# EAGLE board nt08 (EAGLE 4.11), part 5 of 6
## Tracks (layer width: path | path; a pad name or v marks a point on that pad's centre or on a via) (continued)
SH_DTB  (via drill 0.61) (continued)
  Top 0.254: IC100.3 438.15,454.66 436.88,455.93 v436.88,458.47 436.88,488.95 438.15,490.22 IC101.3 438.15,492.76 436.88,494.03 436.88,527.05 438.15,528.32 IC102.3 438.15,530.86 440.06,532.76 | 440.06,532.76 440.69,533.4 440.69,535.94 IC102.11 | 440.06,532.76 441.96,530.86 441.96,528.32 441.32,527.68 441.32,501.01 440.69,500.38 IC101.11 | v278.13,247.01 278.13,245.11 IC62.3 | v280.67,247.65 280.67,250.19 IC62.11 280.67,252.73 281.94,254 281.94,287.02 280.67,288.29 IC63.11 280.67,290.83 281.94,292.1 281.94,321.31 278.76,324.49 | v278.13,287.02 278.13,283.21 IC63.3 | v34.29,323.85 34.29,264.16 35.56,262.89 IC13.2 | 278.76,324.49 278.13,323.85 278.13,321.31 IC64.3 | 278.76,324.49 280.67,326.39 IC64.11 | v283.85,332.11 283.85,354.96 285.75,356.87 IC65.6 | v351.79,451.49 351.15,450.85 v351.15,362.58
  Bottom 0.254: v436.88,458.47 438.15,458.47 440.06,460.38 IC100.11 | v278.13,247.01 278.76,247.65 v280.67,247.65 | v278.13,287.02 280.04,288.93 IC63.11 | v34.29,323.85 34.92,323.21 182.25,323.21 184.15,321.31 271.78,321.31 272.42,321.94 276.23,321.94 277.5,320.68 IC64.3 | v283.85,332.11 280.67,328.93 IC64.11 | v351.79,451.49 436.25,451.49 437.51,452.75 IC100.3 | v351.15,362.58 288.93,362.58 285.75,359.41 IC65.6
SH_EN  (via drill 0.61)
  Top 0.254: v194.94,27.3 194.94,11.43 78.74,11.43 75.56,14.61 IC16.2 | IC105.1 472.44,43.18 472.44,38.1 v461.01,26.67 461.01,4.45 473.07,4.45 474.35,5.71 IC104.2 | v177.8,483.87 184.15,490.22 184.15,549.91 212.72,578.49 350.52,578.49 | 350.52,578.49 v379.73,578.49 | v353.06,26.67 353.69,27.3 353.69,54.61 354.96,55.88 354.96,148.59 354.33,149.22 354.33,276.23 351.79,278.76 351.79,330.83 349.88,332.74 349.88,488.95 350.52,489.58 350.52,578.49
  Bottom 0.254: v194.94,27.3 195.58,26.67 285.12,26.67 285.75,26.04 353.06,26.04 | 353.06,26.04 460.38,26.04 v461.01,26.67 | v177.8,483.87 35.56,483.87 35.56,478.79 36.2,478.15 36.83,478.15 36.83,473.71 IC15.2 | v379.73,578.49 382.27,575.95 433.7,575.95 434.98,577.22 IC103.2 | v353.06,26.67 353.06,26.04
SH_EN\  (via drill 0.61)
  Top 0.254: IC104.4 480.69,5.71 481.96,4.45 483.87,4.45 483.87,49.53 485.14,50.8 IC105.9 | v80.01,273.05 80.01,260.35 78.74,259.08 78.74,242.57 79.38,241.94 79.38,100.97 80.01,100.33 IC17.11 | v36.83,282.57 36.83,443.87 34.29,446.4 34.29,471.17 IC15.1 | v36.2,546.74 31.75,542.29 v31.75,476.25 | v361.95,68.58 v366.39,64.14 | v147.32,73.66 128.27,92.71 v128.27,95.25
  Bottom 0.254: v80.01,273.05 70.48,282.57 v36.83,282.57 | v36.2,546.74 72.39,546.74 95.89,570.23 247.65,570.23 249.56,568.33 300.99,568.33 304.8,572.13 444.5,572.13 444.5,579.12 443.87,579.75 442.6,579.75 441.32,578.49 IC103.4 | v31.75,476.25 34.29,473.71 IC15.1 | v366.39,64.14 473.07,64.14 484.5,52.7 IC105.9 | v361.95,68.58 361.31,69.22 199.39,69.22 194.94,73.66 v147.32,73.66 | v128.27,95.25 122.56,100.97 81.92,100.97 80.64,99.69 IC17.11
SKP_RQ\  (via drill 0.61)
  Top 0.254: v92.71,191.13 92.71,100.33 85.09,92.71 IC17.6 | v184.78,193.68 186.06,194.94 186.06,312.42 186.69,313.06 v186.69,377.19 | v211.46,379.1 212.09,379.73 212.09,548 208.28,551.82 208.28,554.99 IC45.8
  Bottom 0.254: v92.71,191.13 95.25,193.68 v184.78,193.68 | v186.69,377.19 188.59,379.1 v211.46,379.1
SP_DY\  (via drill 0.61)
  Top 0.254: v515.62,146.05 515.62,121.92 518.16,119.38 IC114.12 | v-11.43,165.74 -19.05,173.35 -19.05,222.88 -26.04,229.87 -26.04,233.68 M916_20.F2
  Bottom 0.254: v515.62,146.05 514.99,146.69 412.12,146.69 406.4,152.4 374.65,152.4 370.2,156.84 267.97,156.84 259.08,165.74 v-11.43,165.74
ST_BLK_MK  (via drill 0.61)
  Top 0.254: v433.07,438.15 435.61,440.69 IC99.13 | v291.46,435.61 290.19,436.88 v290.19,445.77
  Bottom 0.254: v433.07,438.15 432.44,437.51 321.94,437.51 320.04,435.61 v291.46,435.61 | v290.19,445.77 288.93,447.04 252.73,447.04 252.09,446.4 67.31,446.4 64.77,443.87 64.77,440.69 M916_10.K1
ST_BLK_MK\  (via drill 0.61)
  Top 0.254: 45.09,18.41 45.72,19.05 45.72,21.59 IC9.9 | 45.09,18.41 v44.45,17.78 | v434.34,421 434.34,436.88 438.15,440.69 IC99.12 | v144.78,413.38 140.34,408.94 v140.34,406.4 | v61.59,398.78 61.59,252.73 60.33,251.46 v60.33,194.31 | v57.15,191.13 55.88,189.87 55.88,168.91 53.98,167 53.98,125.09 55.88,123.19 55.88,20.32 48.9,13.34 46.99,13.34 46.99,16.51 45.09,18.41
  Bottom 0.254: v44.45,17.78 35.56,17.78 33.66,15.88 IC9.1 | v434.34,421 433.7,420.37 379.1,420.37 372.11,413.38 v144.78,413.38 | v140.34,406.4 132.72,398.78 v61.59,398.78 | v60.33,194.31 v57.15,191.13
ST_CK  (via drill 0.61)
  Top 0.254: v38.1,254 38.1,195.58 IC12.12 | v-22.86,271.78 -22.23,272.42 -22.23,452.12 -11.43,462.92 -11.43,465.45 M916_23.M2 | v254.63,490.22 245.11,480.69 v245.11,453.39 | M916_10.P1 77.47,440.69 77.47,449.58 v80.64,452.75 80.64,453.39 v76.2,457.83
  Bottom 0.254: v38.1,254 37.47,254.63 -5.71,254.63 v-22.86,271.78 | M916_23.P2 -5.08,465.45 -7.62,462.92 M916_23.N2 -8.26,462.92 -10.79,465.45 M916_23.M2 -11.43,465.45 -12.7,464.19 -14.61,464.19 -15.24,463.55 -15.24,457.2 75.56,457.2 v76.2,457.83 | v254.63,490.22 278.76,514.35 363.22,514.35 368.3,509.27 471.17,509.27 471.81,509.9 IC111.1 | v245.11,453.39 244.47,452.75 v80.64,452.75
ST_CK\  (via drill 0.61)
  Top 0.254: v477.52,417.83 473.07,422.27 473.07,507.37 474.98,509.27 IC111.2
  Bottom 0.254: v477.52,417.83 489.58,417.83 490.22,418.46 512.45,418.46 514.99,415.93 IC120.2
ST_CK_0P  (via drill 0.61)
  Top 0.254: v446.4,46.99 447.04,47.62 447.04,125.73 449.58,128.27 v449.58,324.49 449.58,415.29 v450.21,415.93 | v445.77,420.37 445.77,427.99 440.69,433.07 IC99.4
  Bottom 0.254: v446.4,46.99 320.04,46.99 315.6,42.55 IC71.13 | v449.58,324.49 450.85,325.75 473.07,325.75 474.35,327.02 IC109.13 | v450.21,415.93 v445.77,420.37
ST_CK_0P\  (via drill 0.61)
  Top 0.254: v435.61,431.17 435.61,431.8 437.51,433.7 IC99.3 | v144.78,427.99 127,445.77 v127,463.55
  Bottom 0.254: v435.61,431.17 433.7,429.26 276.86,429.26 275.59,427.99 v144.78,427.99 | v127,463.55 126.36,464.19 -3.81,464.19 -6.99,461.01 -12.06,461.01 -13.34,462.28 M916_23.L2
ST_DATA  (via drill 0.61)
  Top 0.254: v409.57,-1.91 409.57,211.46 410.21,212.09 410.21,298.45 409.57,299.08 409.57,346.07 412.12,348.62 412.12,391.16 v415.93,394.97 | v523.24,403.23 525.78,405.76 525.78,414.02 IC120.6 | v472.44,403.23 472.44,508 473.71,509.27 473.71,512.45 475.62,512.45 476.88,511.18 IC111.3
  Bottom 0.254: v409.57,-1.91 314.32,-1.91 313.06,-3.17 IC70.1 | v415.93,394.97 424.18,403.23 v472.44,403.23 v523.24,403.23
ST_FINAL  (via drill 0.61)
  Top 0.254: v-40.01,80.01 -40.64,80.64 v-40.64,395.61 | v73.66,482.6 73.66,437.51 M916_10.N1
  Bottom 0.254: v-40.01,80.01 -22.86,62.87 41.27,62.87 42.55,61.59 IC10.10 | v-40.64,395.61 -6.99,429.26 50.8,429.26 53.98,432.44 66.67,432.44 71.12,436.88 73.03,436.88 M916_10.N1 | v73.66,482.6 213.36,482.6 214.63,481.33 283.21,481.33 284.48,482.6 394.97,482.6 396.88,480.69 IC90.12
ST_FINAL\  (via drill 0.61)
  Top 0.254: v468,189.87 466.09,191.77 v466.09,273.05 | v520.7,280.67 520.07,281.31 520.07,318.13 519.43,318.77 519.43,412.75 520.7,414.02 IC120.4
  Bottom 0.254: v468,189.87 471.81,189.87 474.35,187.32 IC107.2 | v466.09,273.05 473.71,280.67 v520.7,280.67
ST_IDLE  (via drill 0.61)
  Top 0.254: v482.6,449.58 482.6,509.27 IC111.5
  Bottom 0.254: v482.6,449.58 480.69,447.68 447.68,447.68 447.04,448.31 373.38,448.31 371.48,446.4 333.38,446.4 331.47,444.5 85.09,444.5 80.64,440.06 80.64,437.51 M916_10.R1
ST_IDLE\  (via drill 0.61)
  Top 0.254: v44.45,19.05 43.18,20.32 43.18,21.59 IC9.10 | v485.14,453.39 485.14,509.27 IC111.6 | v-33.66,426.08 -34.29,425.45 -34.29,37.47 -29.21,32.38 -29.21,19.68 -26.67,17.14 34.92,17.14 34.92,15.88 IC9.2
  Bottom 0.254: v44.45,19.05 45.72,19.05 45.72,17.78 44.45,16.51 43.81,17.14 37.47,17.14 36.2,15.88 IC9.2 | v485.14,453.39 481.96,450.21 307.34,450.21 302.89,454.66 53.34,454.66 51.44,452.75 -6.99,452.75 v-33.66,426.08
ST_REV_CK  (via drill 0.61)
  Top 0.254: IC140.5 602.62,528.96 601.35,528.96 IC140.4 600.71,528.32 593.09,520.7 v593.09,502.29 | v283.21,482.6 283.21,472.44 284.48,471.17 IC68.5 284.48,468.63 284.48,452.12 v278.13,445.77 | v405.13,447.04 405.13,469.9 406.4,471.17 406.4,473.71 405.13,474.98 405.13,478.79 IC90.9
  Bottom 0.254: v283.21,482.6 283.85,483.24 403.86,483.24 405.13,481.96 | 405.13,481.96 405.13,481.33 IC90.9 | v405.13,447.04 405.76,447.68 441.32,447.68 445.77,443.23 IC99.9 | v278.13,445.77 67.94,445.77 67.94,437.51 M916_10.L1 | v593.09,502.29 592.46,501.65 528.96,501.65 502.92,475.62 414.65,475.62 408.31,481.96 405.13,481.96
SWTM  (via drill 0.61)
  Top 0.254: v485.14,17.14 486.41,18.41 486.41,54.61 490.22,58.42 490.22,235.59 | 490.22,235.59 v489.58,236.22 | v490.86,370.84 490.22,370.2 490.22,235.59 | IC55.4 240.03,509.27 v240.03,430.53 240.03,405.13 IC54.11 240.03,402.59 241.3,401.32 241.3,381.63 v245.11,377.82 | v83.82,297.18 92.08,305.44 92.08,363.86 92.71,364.49 92.71,415.93 91.44,417.19 91.44,429.89 92.08,430.53 M916_10.V2
  Bottom 0.254: v485.14,17.14 484.5,17.14 482.6,15.24 IC104.10 | v489.58,236.22 495.3,241.94 518.79,241.94 520.07,243.21 IC117.4 | v490.86,370.84 481.33,370.84 475.62,376.56 IC110.2 474.35,376.56 468,370.2 333.38,370.2 325.75,377.82 v245.11,377.82 | v83.82,297.18 5.08,297.18 0.64,292.74 IC2.4 | v240.03,430.53 93.34,430.53 M916_10.V2
SWTM\  (via drill 0.61)
  Top 0.254: v490.86,387.99 492.12,386.71 492.12,328.93 490.86,327.66 490.86,112.39 493.39,109.86 493.39,5.71 491.49,3.81 478.79,3.81 478.79,11.43 477.52,12.7 IC104.12
  Bottom 0.254: v490.86,387.99 419.1,387.99 408.94,398.14 407.04,398.14 403.23,401.95 244.47,401.95 243.21,403.23 IC54.10
SYNC
  Top 0.254: IC66.10 283.85,403.23 285.12,403.23 IC66.9
SYNC-P\  (via drill 0.61)
  Top 0.254: IC73.1 312.42,113.03 314.96,115.57 314.96,118.11 IC73.13 314.96,120.65 312.42,123.19 312.42,166.37 IC74.1 312.42,168.91 314.96,171.45 314.96,173.99 IC74.13 314.96,176.53 312.42,179.07 312.42,186.69 IC75.1 312.42,189.23 314.96,191.77 314.96,194.31 IC75.13 | v289.56,361.31 289.56,367.03 288.93,367.67 288.93,393.7 289.56,394.33 289.56,401.32 288.29,402.59 IC66.8 | v309.25,358.77 310.51,357.5 v310.51,196.85
  Bottom 0.254: v289.56,361.31 292.1,358.77 v309.25,358.77 | v310.51,196.85 311.15,197.49 313.06,197.49 314.32,196.22 IC75.13
T3  (via drill 0.61)
  Top 0.254: v544.83,471.17 544.83,420.37 546.1,419.1 546.1,120.65 551.18,115.57 551.18,20.32 554.99,16.51 IC123.2
  Bottom 0.254: v544.83,471.17 570.87,497.2 596.26,497.2 | 596.26,497.2 597.53,498.48 IC139.12 | 596.26,497.2 601.35,497.2 602.62,498.48 IC139.10
T_00\  (via drill 0.61)
  Top 0.254: v313.69,287.02 v313.69,284.48 | M916_16.V2 372.75,208.91 373.38,209.55 373.38,283.85 372.75,284.48 M916_17.V2
  Bottom 0.254: v313.69,284.48 132.72,284.48 M916_8.V2 | v313.69,287.02 316.23,289.56 363.86,289.56 368.3,285.12 371.48,285.12 M916_17.V2
T_01\  (via drill 0.61)
  Top 0.254: v121.92,221.62 121.92,218.44 M916_7.S1 | v109.22,222.88 108.58,223.52 108.58,283.21 109.22,283.85 109.22,287.65 M916_8.M2 110.49,288.29 111.12,288.93 111.12,337.19 v114.94,341 | v347.35,337.82 347.35,296.55 347.98,295.91 347.98,289.56 349.25,288.29 M916_17.M2
  Bottom 0.254: v121.92,221.62 120.65,222.88 v109.22,222.88 | v347.35,337.82 341,344.17 187.96,344.17 186.06,342.26 116.2,342.26 v114.94,341
T_02\  (via drill 0.61)
  Top 0.254: v103.5,284.48 98.42,279.4 98.42,212.72 97.79,212.09 M916_7.H2
  Bottom 0.254: v103.5,284.48 105.41,286.38 111.12,286.38 | 111.12,286.38 112.39,285.12 M916_8.N2 | 111.12,286.38 132.72,286.38 133.99,285.12 313.06,285.12 314.32,286.38 351.15,286.38 352.43,285.12 M916_17.N2
T_03\  (via drill 0.61)
  Top 0.254: v106.68,279.4 107.31,278.76 107.31,276.23 104.78,273.69 104.78,208.91 100.97,208.91 M916_7.J2 | v116.2,279.4 116.2,287.65 M916_8.P2 | v356.87,259.08 356.87,287.65 M916_17.P2 | v290.19,249.56 v290.19,257.81 | v170.18,249.56 168.28,251.46 v168.28,273.05
  Bottom 0.254: v106.68,279.4 v116.2,279.4 121.92,273.69 167.64,273.69 v168.28,273.05 | v356.87,259.08 356.24,258.44 295.27,258.44 294.64,257.81 v290.19,257.81 | v290.19,249.56 173.35,249.56 172.72,250.19 170.81,250.19 v170.18,249.56
T_04\  (via drill 0.61)
  Top 0.254: v110.49,280.67 110.49,249.56 111.12,248.92 111.12,219.71 111.76,219.07 111.76,209.55 112.39,208.91 M916_7.N2 | v118.75,281.94 118.75,284.48 M916_8.R2 | v334.64,280.67 332.11,278.13 v332.11,276.86 | v243.21,276.86 245.11,274.95 v245.11,272.42
  Bottom 0.254: v118.75,281.94 111.76,281.94 v110.49,280.67 105.41,280.67 105.41,279.4 114.3,270.51 179.71,270.51 181.61,268.61 245.11,268.61 v245.11,272.42 | v334.64,280.67 354.96,280.67 358.77,284.48 M916_17.R2 | v332.11,276.86 331.47,277.5 243.84,277.5 v243.21,276.86
T_05\  (via drill 0.61)
  Top 0.254: v114.3,232.41 114.3,213.36 115.57,212.09 M916_7.P2 | v121.92,233.04 123.19,234.31 123.19,259.71 | 123.19,259.71 123.19,287.65 M916_8.S2 | v361.95,256.54 361.95,287.65 M916_17.S2 | v122.56,259.71 123.19,259.71
  Bottom 0.254: v114.3,232.41 114.94,233.04 v121.92,233.04 | v361.95,256.54 360.68,255.27 287.02,255.27 285.75,256.54 168.28,256.54 165.1,259.71 v122.56,259.71
T_06\  (via drill 0.61)
  Top 0.254: M916_8.T2 125.09,284.48 123.83,283.21 123.83,207.01 127.64,207.01 128.91,208.28 128.91,211.46 M916_7.U2 129.54,211.46 v132.08,211.46 | v362.58,220.34 362.58,229.87 366.39,233.68 366.39,284.48 M916_17.T2 | v147.32,217.17 146.69,216.53 v146.69,214
  Bottom 0.254: v362.58,220.34 361.95,219.71 291.46,219.71 289.56,217.81 276.86,217.81 275.59,216.53 147.96,216.53 v147.32,217.17 | v146.69,214 144.15,211.46 v132.08,211.46
T_07\  (via drill 0.61)
  Top 0.254: v127.64,208.28 127,208.91 127,217.81 124.46,220.34 124.46,260.99 | 124.46,260.99 124.46,281.31 128.27,285.12 128.27,287.65 M916_8.U2 | v368.3,261.62 368.3,287.65 M916_17.U2 | v125.09,260.99 124.46,260.99
  Bottom 0.254: v127.64,208.28 131.44,208.28 M916_7.V2 | v368.3,261.62 367.03,260.35 319.4,260.35 318.13,259.08 294.64,259.08 294,258.44 290.83,258.44 289.56,259.71 244.47,259.71 241.94,257.18 177.16,257.18 173.35,260.99 v125.09,260.99
T_FWD\  (via drill 0.61)
  Top 0.254: v90.81,219.71 89.53,220.98 89.53,244.47 90.81,245.75 90.81,265.43 | 90.81,265.43 90.81,287.65 M916_8.E2 | v336.55,271.14 336.55,287.65 M916_17.H2 | v91.44,265.43 90.81,265.43
  Bottom 0.254: v90.81,219.71 97.79,219.71 98.42,219.07 102.23,219.07 102.87,218.44 M916_7.K1 | v336.55,271.14 334.01,268.61 247.65,268.61 246.38,267.33 142.24,267.33 140.97,266.06 92.08,266.06 v91.44,265.43
T_GO\  (via drill 0.61)
  Top 0.254: v327.02,300.36 326.39,299.72 326.39,285.75 327.02,285.12 M916_17.D2 | v101.6,302.26 v97.16,297.81
  Bottom 0.254: v327.02,300.36 326.39,300.99 257.81,300.99 257.18,301.62 103.5,301.62 102.87,302.26 v101.6,302.26 | v97.16,297.81 87.63,288.29 85.09,288.29 M916_8.C2
T_PWR_CLR\  (via drill 0.61)
  Top 0.254: v115.57,290.83 114.94,290.19 114.94,279.4 117.47,276.86 v117.47,271.78 117.47,216.53 118.75,215.26 M916_7.R1 | v343.54,272.42 343.54,287.65 M916_17.K2
  Bottom 0.254: v115.57,290.83 113.67,292.74 104.14,292.74 99.69,288.29 97.79,288.29 M916_8.H2 | v343.54,272.42 327.02,272.42 326.39,273.05 326.39,276.23 284.48,276.23 281.94,273.69 170.18,273.69 168.28,271.78 v117.47,271.78
T_REV\  (via drill 0.61)
  Top 0.254: v107.95,283.85 107.95,215.9 107.31,215.26 M916_7.L1
  Bottom 0.254: 107.31,283.21 v107.95,283.85 | 107.31,283.21 95.89,283.21 94.61,284.48 M916_8.F2 | 107.31,283.21 132.72,283.21 133.35,283.85 288.93,283.85 289.56,283.21 338.45,283.21 339.73,284.48 M916_17.J2
T_SINGLE_UNIT\  (via drill 0.61)
  Top 0.254: v140.34,286.38 139.7,285.75 139.7,222.25 140.97,220.98 140.97,135.89 v140.34,135.25
  Bottom 0.254: v140.34,286.38 137.16,289.56 105.41,289.56 104.14,288.29 M916_8.K2 | v140.34,135.25 245.11,135.25 249.56,130.81 363.86,130.81 365.12,132.08 M916_15.T2
T_STOP\  (via drill 0.61)
  Top 0.254: M916_7.E1 90.17,218.44 88.9,219.71 88.9,245.11 90.17,246.38 90.17,282.57 88.27,284.48 M916_8.D2 | v330.83,271.14 330.83,287.65 M916_17.E2
  Bottom 0.254: v330.83,271.14 328.93,269.24 288.93,269.24 285.75,272.42 250.19,272.42 245.75,267.97 104.78,267.97 88.27,284.48 M916_8.D2
T_TRK  (via drill 0.61)
  Top 0.254: v265.43,194.31 v265.43,225.43 265.43,252.73 v267.33,254.63 | 12.7,257.81 7.62,252.73 7.62,243.84 M916_20.U1 | 12.7,257.81 v13.97,259.08 | v515.62,309.25 515.62,318.77 IC118.2 | v381.63,309.25 377.82,305.44 v377.82,226.06 | 12.7,257.81 12.7,302.89 14.61,304.8 14.61,473.07 11.43,473.07 10.16,474.35 10.16,476.88 8.89,478.15 M916_3.U2
  Bottom 0.254: v265.43,194.31 267.33,192.41 273.69,192.41 274.95,193.68 IC61.13 | v267.33,254.63 266.06,255.91 167.64,255.91 165.1,258.44 14.61,258.44 v13.97,259.08 | v381.63,309.25 v515.62,309.25 | v377.82,226.06 266.06,226.06 v265.43,225.43 | M916_20.S1 2.54,243.21 7.62,243.21 M916_20.U1
T_TRK\  (via drill 0.61)
  Top 0.254: v283.21,205.1 283.21,195.58 IC61.10 | v260.35,212.72 254.63,218.44 254.63,304.8 253.37,306.07 v253.37,374.01 | v15.88,387.35 15.24,387.99 15.24,473.71 13.97,474.98 12.06,474.98 M916_3.V2
  Bottom 0.254: v283.21,205.1 275.59,212.72 v260.35,212.72 | v253.37,374.01 251.46,375.92 118.11,375.92 106.68,387.35 v15.88,387.35
T_WRITE_OK\  (via drill 0.61)
  Top 0.254: 99.06,247.01 99.06,275.59 v103.5,280.04 | 99.06,247.01 99.06,212.09 98.42,211.46 98.42,136.53 97.79,135.89 M916_6.H2 | v106.05,281.94 106.05,284.48 M916_8.L2 | v347.35,256.54 347.35,284.48 M916_17.L2 | v269.24,257.81 264.16,252.73 v264.16,250.82 | v99.69,247.01 99.06,247.01
  Bottom 0.254: v103.5,280.04 105.41,281.94 v106.05,281.94 | v347.35,256.54 346.71,255.91 287.65,255.91 286.38,257.18 269.88,257.18 v269.24,257.81 | v264.16,250.82 263.52,250.19 173.99,250.19 173.35,250.82 168.28,250.82 165.1,247.65 100.33,247.65 v99.69,247.01
TIM  (via drill 0.61)
  Top 0.254: v48.26,460.38 48.26,496.57 44.45,500.38 IC6.5 | v125.73,459.11 125.09,458.47 125.09,374.01 128.27,370.84 M916_9.U1
  Bottom 0.254: v48.26,460.38 49.53,459.11 v125.73,459.11
TIM\  (via drill 0.61)
  Top 0.254: v38.1,131.44 38.1,120.65 36.83,119.38 36.83,116.84 34.29,114.3 34.29,55.88 35.56,54.61 IC10.2 | v121.92,147.32 122.56,147.96 v122.56,201.29 v122.56,207.65 | v60.33,488.31 60.33,440.06 62.87,437.51 62.87,266.7 62.23,266.06 62.23,201.93 v61.59,201.29
  Bottom 0.254: v38.1,131.44 53.98,147.32 v121.92,147.32 | v122.56,207.65 125.09,210.19 129.54,210.19 134.62,215.26 198.75,215.26 200.03,214 IC38.11 | v60.33,488.31 47.62,501.01 IC6.6 | v61.59,201.29 v122.56,201.29
TM_EN  (via drill 0.61)
  Top 0.254: IC117.11 520.7,252.73 523.24,255.27 523.24,317.5 524.51,318.77 524.51,382.27 525.78,383.54 IC119.9 | v514.35,388.62 514.35,450.85 513.08,452.12 IC121.1 | v488.95,464.19 488.95,520.07 487.05,520.07 485.77,518.79 IC111.9 485.14,519.43 485.14,526.41 v457.83,553.72 | v-1.27,544.83 -1.27,538.48 -2.54,537.21 -2.54,476.25 -1.91,475.62 M916_3.R2
  Bottom 0.254: v514.35,388.62 516.25,386.71 523.88,386.71 525.14,385.44 IC119.9 | v488.95,464.19 499.11,454.02 512.45,454.02 IC121.1 | v-1.27,544.83 -0.64,545.47 89.53,545.47 109.22,565.15 314.32,565.15 318.13,568.96 | 318.13,568.96 319.4,570.23 M916_13.R2 | v457.83,553.72 442.6,568.96 318.13,568.96
TM_EN\  (via drill 0.61)
  Top 0.254: v476.25,323.85 476.25,318.77 474.98,317.5 474.98,271.78 IC108.13 | IC111.8 487.68,516.89 483.87,513.08 483.87,330.2 482.6,328.93 IC109.10 | v128.91,314.96 134.62,309.25 v134.62,282.57 | v283.21,276.23 282.57,275.59 282.57,253.37 281.94,252.73 281.94,219.71 285.75,215.9 285.75,195.58 IC61.9
  Bottom 0.254: v476.25,323.85 478.79,326.39 478.79,329.56 480.69,329.56 481.96,328.3 IC109.10 | M916_21.J2 -19.68,310.51 -17.14,313.06 M916_21.K2 -16.51,313.69 -16.51,318.13 47.62,318.13 50.8,314.96 v128.91,314.96 | IC61.12 278.76,193.68 280.04,192.41 283.85,192.41 285.12,193.68 IC61.9 | v134.62,282.57 142.24,274.95 242.57,274.95 243.84,276.23 v283.21,276.23 283.85,276.86 327.66,276.86 330.2,274.32 349.88,274.32 350.52,274.95 434.34,274.95 437.51,271.78 466.09,271.78 466.73,272.42 473.07,272.42 474.35,271.14 IC108.13
TP00  (via drill 0.61)
  Top 0.254: IC73.3 317.5,113.03 320.04,115.57 320.04,118.11 IC73.11 319.4,120.02 319.4,164.47 317.5,166.37 IC74.3 317.5,168.91 v317.5,172.72 | v522.61,180.34 522.61,201.29 523.24,201.93 IC116.5 | v290.83,361.31 290.19,361.95 v290.19,393.7 | v275.59,393.06 275.59,394.97 IC66.2 275.59,397.51 275.59,402.59 IC66.13 275.59,405.13 v275.59,429.26 | v65.41,253.37 65.41,407.67 66.04,408.31 66.04,414.02 v64.77,415.29 | v-1.91,427.99 -1.91,440.06 -2.54,440.69 IC5.3 | M916_2.M2 71.12,421 73.03,419.1 73.03,418.46 M916_2.N2 | v308.61,173.35 307.34,174.62 307.34,196.22 308.61,197.49 308.61,356.87 307.98,357.5 v307.98,361.31
  Bottom 0.254: v522.61,180.34 427.99,180.34 426.08,182.25 344.17,182.25 334.64,172.72 v317.5,172.72 316.87,173.35 v308.61,173.35 | v290.83,361.31 v307.98,361.31 311.79,361.31 314.32,358.77 IC78.2 | v290.19,393.7 289.56,393.06 v275.59,393.06 | IC66.12 277.5,403.23 276.23,403.23 IC66.13 | v65.41,253.37 85.72,253.37 87,252.09 IC18.8 | M916_2.N2 73.03,417.83 71.75,416.56 66.04,416.56 v64.77,415.29 48.9,415.29 37.47,426.72 -0.64,426.72 v-1.91,427.99 | M916_2.M2 71.12,421 76.2,421 M916_2.P2 77.47,421.64 78.74,422.91 87,422.91 93.34,429.26 v275.59,429.26
TP00\  (via drill 0.61)
  Top 0.254: IC18.13 75.56,250.82 76.83,250.82 IC18.12 | IC18.10 83.19,250.82 84.45,250.82 IC18.9 85.09,250.19 85.09,245.11 IC18.6 | v318.77,201.93 318.77,194.31 318.13,193.68 318.13,189.87 317.5,189.23 IC75.3 | v182.88,206.38 v182.88,251.46
  Bottom 0.254: v318.77,201.93 318.13,201.29 276.86,201.29 276.23,200.66 188.59,200.66 v182.88,206.38 | v182.88,251.46 167.64,251.46 164.47,248.28 89.53,248.28 85.72,244.47 IC18.6 | IC18.12 78.11,250.82 79.38,249.56 80.64,249.56 81.92,250.82 IC18.10
TP00_A  (via drill 0.61)
  Top 0.254: v169.54,265.43 170.18,266.06 v170.18,372.75 | v280.67,373.38 283.21,370.84 283.21,367.03 IC65.10 | v478.79,357.5 478.79,322.58 480.06,321.31 IC109.4 | v331.47,370.84 v344.81,357.5
  Bottom 0.254: v169.54,265.43 93.98,265.43 92.71,264.16 88.9,264.16 87,262.25 IC19.6 | v170.18,372.75 262.25,372.75 262.89,373.38 v280.67,373.38 328.93,373.38 v331.47,370.84 | v344.81,357.5 v478.79,357.5
TP00_A\  (via drill 0.61)
  Top 0.254: IC19.1 74.3,260.99 75.56,260.99 IC19.2 | v63.5,266.06 63.5,417.83 66.67,417.83 M916_2.L2
  Bottom 0.254: IC19.5 83.19,260.99 81.92,260.99 IC19.4 80.64,262.25 79.38,263.52 78.11,263.52 76.83,262.25 IC19.2 | v63.5,266.06 67.31,262.25 73.03,262.25 IC19.1
TP0_XTLK_DY\  (via drill 0.61)
  Top 0.254: 65.41,421 64.77,421 M916_2.K2 | 65.41,421 66.67,421 68.58,419.1 68.58,321.31 77.47,312.42 77.47,308.61 76.83,307.98 76.83,272.42 78.74,270.51 IC19.12 | v61.59,465.45 65.41,461.64 65.41,421
  Bottom 0.254: v61.59,465.45 53.98,465.45 47.62,471.81 IC15.6 | M916_2.J2 60.33,418.46 59.69,419.1 57.78,419.1 56.52,420.37 56.52,422.91 62.23,422.91 63.5,421.64 M916_2.K2
TP01  (via drill 0.61)
  Top 0.254: v482.6,167 482.6,119.38 IC106.10 | v515.62,177.16 514.99,177.8 514.99,202.56 IC116.2 | M916_12.N2 313.06,494.67 311.15,496.57 311.15,497.2 M916_12.M2 | v54.61,23.5 49.53,28.57 49.53,73.03 | 49.53,73.03 49.53,74.93 48.9,75.56 48.9,108.58 49.53,109.22 v49.53,317.5 | v86.36,493.39 84.45,491.49 84.45,372.75 86.36,370.84 86.36,322.58 85.09,321.31 IC20.6 | v306.07,108.58 302.89,105.41 v302.89,76.2 | 49.53,73.03 v51.44,74.93
  Bottom 0.254: v482.6,167 492.76,177.16 v515.62,177.16 | M916_12.P2 316.23,497.2 313.69,494.67 M916_12.N2 313.06,494.03 307.98,488.95 203.84,488.95 199.39,493.39 v86.36,493.39 | v54.61,23.5 57.15,20.95 80.64,20.95 81.92,22.23 IC16.10 | v49.53,317.5 50.16,318.13 83.19,318.13 84.45,319.4 IC20.6 | v306.07,108.58 327.02,108.58 338.45,120.02 438.79,120.02 442.6,116.2 480.69,116.2 481.96,117.47 IC106.10 | v302.89,76.2 301.62,74.93 v51.44,74.93
TP01\  (via drill 0.61)
  Top 0.254: IC20.1 73.03,319.4 74.3,319.4 IC20.2 | 82.55,267.33 87,267.33 88.27,268.61 IC19.8 | 82.55,267.33 82.55,318.77 IC20.5 | v75.56,179.71 74.93,180.34 74.93,241.3 73.66,242.57 v73.66,246.38 | v80.01,247.65 81.28,248.92 81.28,259.08 82.55,260.35 82.55,267.33
  Bottom 0.254: IC20.5 81.92,319.4 80.64,319.4 IC20.4 79.38,320.68 78.11,321.94 76.83,321.94 75.56,320.68 IC20.2 | v75.56,179.71 136.53,179.71 137.79,178.44 178.44,178.44 181.61,175.26 304.17,175.26 306.07,177.16 318.13,177.16 319.4,175.9 IC74.11 | v73.66,246.38 74.93,247.65 v80.01,247.65
TP01_A  (via drill 0.61)
  Top 0.254: v361.95,81.92 370.2,90.17 370.2,143.51 364.49,149.22 v364.49,230.5 | v180.34,330.2 184.15,326.39 v184.15,322.58 | v371.48,323.85 370.84,323.21 370.84,231.14 v371.48,230.5
  Bottom 0.254: v361.95,81.92 349.25,81.92 345.44,78.11 319.4,78.11 318.13,79.38 IC72.12 | v364.49,230.5 v371.48,230.5 452.75,230.5 475.62,253.37 521.34,253.37 522.61,252.09 IC117.10 | v180.34,330.2 90.17,330.2 88.27,328.3 IC20.8 | v184.15,322.58 294.64,322.58 295.91,323.85 v371.48,323.85
TP01_A\  (via drill 0.61)
  Top 0.254: IC20.13 75.56,327.02 76.83,327.02 IC20.12 | IC20.10 83.19,327.02 84.45,327.02 IC20.9 | v300.99,341 300.99,488.31 306.7,494.03 M916_12.L2
  Bottom 0.254: v300.99,341 300.36,341.63 206.38,341.63 197.49,332.74 90.17,332.74 87,329.56 | 87,329.56 85.72,328.3 IC20.9 | 87,329.56 79.38,329.56 78.11,328.3 IC20.12
TP1_XTLK_DY\  (via drill 0.61)
  Top 0.254: M916_12.H2 298.45,497.2 300.36,495.3 300.36,494.67 M916_12.J2 300.36,494.03 297.18,490.86 v297.18,455.93 | v52.07,482.6 52.7,481.96 v52.7,455.3 52.7,419.74 51.44,418.46 v51.44,247.65
  Bottom 0.254: v52.07,482.6 41.91,482.6 40.01,480.69 IC15.12 | v51.44,247.65 53.34,245.75 73.03,245.75 74.3,244.47 IC18.2 | v297.18,455.93 296.55,455.3 v52.7,455.3
TS03\  (via drill 0.61)
  Top 0.254: v327.66,382.27 v327.66,451.49 | M916_23.H2 -22.86,465.45 -20.95,463.55 -20.95,462.92 M916_23.J2 -19.68,462.92 -19.68,463.55 -17.78,465.45 M916_23.K2
  Bottom 0.254: v327.66,382.27 392.43,382.27 396.88,377.82 IC88.3 | v327.66,451.49 321.94,457.2 76.83,457.2 76.2,456.56 -15.88,456.56 -19.68,460.38 -19.68,462.28 M916_23.J2
U+M_DY\  (via drill 0.61)
  Top 0.254: v-29.21,241.94 -29.21,237.49 M916_20.E2 | v468.63,377.19 v468.63,319.4 468.63,267.97 472.44,264.16 IC108.1 | v384.18,325.12 386.08,323.21 v386.08,320.04
  Bottom 0.254: M916_20.N1 -8.26,240.66 -9.53,241.94 v-29.21,241.94 -30.48,241.94 -43.81,255.27 -43.81,325.75 73.03,325.75 74.3,324.49 274.95,324.49 275.59,325.12 v384.18,325.12 | v468.63,377.19 474.98,383.54 IC110.13 | v386.08,320.04 386.71,319.4 v468.63,319.4
USR_00  (via drill 0.61)
  Top 0.254: v78.11,273.69 78.74,274.32 78.74,286.38 79.38,287.02 79.38,318.13 78.74,318.77 78.74,362.58 79.38,363.22 79.38,369.57 78.74,370.2 M916_9.A1 | v114.94,518.79 97.16,501.01 v97.16,386.08
  Bottom 0.254: v78.11,273.69 -0.64,273.69 -8.26,266.06 IC1.22 | v114.94,518.79 135.25,539.12 235.59,539.12 236.85,537.85 IC56.12 | v97.16,386.08 81.92,370.84 78.74,370.84 M916_9.A1
USR_00\  (via drill 0.61)
  Top 0.254: v153.67,517.52 153.67,477.52 151.13,474.98 151.13,401.32 154.94,397.51 IC30.2 | v234.31,522.61 233.68,523.24 233.68,531.5 234.95,532.76 234.95,535.94 IC56.13
  Bottom 0.254: v153.67,517.52 158.75,522.61 v234.31,522.61
USR_01  (via drill 0.61)
  Top 0.254: v11.43,272.42 12.06,273.05 12.06,308.61 12.7,309.25 12.7,346.71 v12.06,347.35 | v80.64,537.85 74.93,532.13 v74.93,368.3
  Bottom 0.254: v11.43,272.42 0.64,272.42 -5.71,266.06 IC1.21 | v12.06,347.35 33.02,368.3 v74.93,368.3 80.01,368.3 80.64,367.67 M916_9.B1 | v80.64,537.85 82.55,539.75 242.57,539.75 244.47,537.85 IC56.9
USR_01\  (via drill 0.61)
  Top 0.254: v162.56,391.16 162.56,394.97 IC30.5 | v257.18,391.16 261.62,395.61 261.62,476.88 264.16,479.43 264.16,519.43 247.65,535.94 IC56.8
  Bottom 0.254: v257.18,391.16 v162.56,391.16
USR_02  (via drill 0.61)
  Top 0.254: v-3.81,271.78 -3.81,266.7 IC1.20 | v80.01,283.85 80.01,317.5 81.28,318.77 81.28,358.77 83.19,360.68 83.19,369.57 83.82,370.2 M916_9.C1 | v92.08,578.49 87.63,574.04 87.63,427.99 85.09,425.45 85.09,373.38 v86.36,372.11
  Bottom 0.254: v-3.81,271.78 8.26,283.85 v80.01,283.85 | v92.08,578.49 234.31,578.49 236.85,575.95 IC57.12 | v86.36,372.11 85.09,370.84 M916_9.C1
USR_02\  (via drill 0.61)
  Top 0.254: v169.54,573.4 169.54,471.81 168.28,470.54 168.28,463.55 169.54,462.28 169.54,394.33 167,394.33 166.37,394.97 166.37,397.51 167.64,398.78 167.64,402.59 IC30.8
  Bottom 0.254: v169.54,573.4 233.04,573.4 234.31,574.67 IC57.13
USR_02_
  Top 0.254: IC2.12 -2.54,298.45 -1.91,297.81 -1.91,294 -1.27,293.37 -1.27,266.7 IC1.19
  Bottom 0.254: IC1.19 -0.64,264.8 0.64,264.8 IC1.18
UTS  (via drill 0.61)
  Top 0.254: v40.01,114.94 39.37,115.57 v39.37,146.05 | v31.75,153.67 27.94,157.48 27.94,228.6 26.04,230.5 26.04,388.62 | 26.04,388.62 26.04,427.36 v29.21,430.53 | v530.86,342.26 530.86,114.3 529.59,114.3 528.32,115.57 528.32,116.84 IC114.8 | v340.36,352.43 331.47,361.31 v331.47,365.76 | 26.04,388.62 v27.94,388.62 | v280.67,385.44 287.02,379.1 v287.02,369.57
  Bottom 0.254: v40.01,114.94 43.18,111.76 IC11.5 | v31.75,153.67 v39.37,146.05 | v29.21,430.53 30.48,431.8 40.64,431.8 44.45,435.61 58.42,435.61 59.69,436.88 60.33,436.88 M916_10.J1 | v530.86,342.26 521.97,351.15 427.36,351.15 425.45,353.06 341,353.06 v340.36,352.43 | v331.47,365.76 329.56,367.67 327.02,367.67 | 327.02,367.67 325.75,366.39 IC78.9 | v27.94,388.62 28.57,387.99 147.96,387.99 150.5,385.44 v280.67,385.44 | v287.02,369.57 288.93,367.67 327.02,367.67
UTS\  (via drill 0.61)
  Top 0.254: v527.05,221.62 527.05,195.58 524.51,193.04 524.51,120.65 525.78,119.38 IC114.9 | v518.16,230.5 514.35,234.31 514.35,317.5 | 514.35,317.5 513.08,318.77 IC118.1 | 514.35,317.5 514.35,328.93 513.72,329.56 513.72,375.29 513.08,375.92 IC119.1 | v279.4,337.82 279.4,439.42 278.13,440.69 IC67.12
  Bottom 0.254: IC67.13 276.23,441.32 277.5,441.32 IC67.12 278.76,441.32 280.04,440.06 281.31,440.06 282.57,441.32 IC67.10 283.85,441.32 285.12,441.32 IC67.9 | IC119.1 513.72,376.56 514.99,376.56 IC119.2 516.25,376.56 517.52,375.29 518.79,375.29 520.07,376.56 IC119.4 521.34,376.56 522.61,376.56 IC119.5 | 485.14,322.58 485.77,321.94 511.18,321.94 512.45,320.68 IC118.1 | 485.14,322.58 480.69,327.02 IC109.11 | v518.16,230.5 v527.05,221.62 | v279.4,337.82 284.48,332.74 417.83,332.74 427.99,322.58 485.14,322.58
VCC  (via drill 0.61)
  Top 0.254: 591.82,420.37 591.82,387.35 593.09,386.08 IC136.14 593.09,383.54 591.82,382.27 591.82,325.12 | 591.82,420.37 593.09,421.64 IC137.14 | 591.82,458.47 593.09,459.74 IC138.14 | 591.82,420.37 591.82,458.47 | 591.82,496.57 593.09,497.84 IC139.14 | 591.82,458.47 591.82,496.57 | 591.82,534.67 593.09,535.94 IC140.14 | 591.82,496.57 591.82,534.67 | 591.82,534.67 591.82,572.77 593.09,574.04 IC141.14 | 601.98,69.85 601.98,36.83 600.71,35.56 IC126.4 | 601.98,69.85 600.71,71.12 IC127.4 | 601.98,69.85 601.98,107.95 600.71,109.22 IC128.4 600.71,111.76 601.98,113.03 601.98,139.06 600.71,140.34 600.71,156.21 601.98,157.48 601.98,161.93 600.71,163.19 600.71,165.1 IC129.11 | IC129.13 595,165.74 593.73,165.74 IC129.14 593.09,167.64 594.36,168.91 594.36,203.84 | 594.36,203.84 595,203.84 IC130.13 | 594.36,203.84 593.73,203.84 IC130.14 | 591.82,273.05 593.09,271.78 IC132.14 | 591.82,287.02 591.82,273.05 | 591.82,287.02 593.09,288.29 IC133.14 | 591.82,306.07 593.09,307.34 IC134.14 | 591.82,306.07 591.82,287.02 | 591.82,325.12 593.09,326.39 IC135.14 | 591.82,325.12 591.82,306.07 | 591.82,273.05 591.82,245.11 593.09,243.84 IC131.14 | IC130.11 600.71,205.74 599.44,207.01 599.44,240.03 600.71,241.3 IC131.11 | 391.16,22.23 391.16,77.47 | 391.16,22.23 391.16,6.35 392.43,5.08 IC83.14 | 391.16,77.47 392.43,78.74 IC84.14 | 391.16,77.47 391.16,144.78 | 391.16,144.78 391.16,153.67 392.43,154.94 IC85.14 392.43,157.48 392.43,201.29 393.7,202.56 393.7,220.98 | 391.16,144.78 v391.8,144.78 | 393.7,220.98 393.7,229.87 392.43,231.14 IC86.14 | v389.89,250.82 390.52,250.19 390.52,224.16 393.7,220.98 | 511.81,115.57 511.81,82.55 513.08,81.28 IC113.14 513.08,78.74 511.81,77.47 511.81,25.4 513.08,24.13 IC112.14
  Top 0.254: 511.81,115.57 513.08,116.84 IC114.14 | 511.81,153.67 513.08,154.94 IC115.14 | 511.81,153.67 511.81,115.57 | 511.81,153.67 511.81,208.28 513.08,209.55 IC116.14 513.08,212.09 512.45,212.72 512.45,241.94 511.81,242.57 511.81,248.92 513.08,250.19 IC117.14 513.08,252.73 511.81,254 511.81,330.2 | 471.17,115.57 472.44,116.84 IC106.14 | 471.17,115.57 471.17,54.61 472.44,53.34 IC105.14 | 471.17,115.57 471.17,191.77 472.44,193.04 IC107.14 | IC104.13 474.98,15.24 476.25,16.51 v476.25,21.59 476.25,49.53 474.98,50.8 IC105.13 | v394.97,22.23 391.16,22.23 | 546.1,521.97 551.82,527.68 IC125.14 | 546.1,521.97 v545.47,521.34 | 546.1,521.97 546.1,438.15 IC124.24 | 511.81,330.2 513.08,328.93 IC118.14 | 511.81,330.2 511.81,382.27 513.08,383.54 IC119.14 513.08,386.08 513.08,412.75 511.81,414.02 511.81,425.45 | 511.81,425.45 513.08,424.18 IC120.14 | 511.81,425.45 v511.81,436.25 511.81,458.47 513.08,459.74 IC121.14 513.08,462.28 511.18,464.19 511.18,514.99 513.08,516.89 IC122.14 | IC108.14 472.44,271.78 471.17,273.05 471.17,325.12 472.44,326.39 IC109.14 472.44,328.93 471.17,330.2 471.17,382.27 472.44,383.54 IC110.14 | IC96.13 435.61,339.09 434.34,340.36 434.34,373.38 435.61,374.65 IC97.13 | IC94.4 440.69,245.11 439.42,246.38 439.42,279.4 440.69,280.67 IC95.4 440.69,283.21 439.42,284.48 439.42,340.36 | 439.42,340.36 440.69,339.09 IC96.11 | 439.42,340.36 439.42,373.38 440.69,374.65 IC97.11 | IC88.14 392.43,386.08 392.43,386.71 393.7,387.99 393.7,401.32 392.43,402.59 IC89.14 392.43,405.13 391.8,405.76 391.8,457.83 v390.52,459.11 390.52,476.88 392.43,478.79 IC90.14 392.43,481.33 391.16,482.6 391.16,496.57 392.43,497.84 IC91.14
  Top 0.254: IC103.13 434.98,584.84 433.7,584.84 IC103.14 433.07,584.2 431.8,582.93 431.8,534.67 | IC98.13 434.98,413.38 433.7,413.38 IC98.14 433.07,415.29 431.8,416.56 | 431.8,444.5 433.07,443.23 IC99.14 | 431.8,458.47 431.8,444.5 | 431.8,458.47 433.07,459.74 IC100.14 | 431.8,496.57 433.07,497.84 IC101.14 | 431.8,496.57 431.8,458.47 | IC82.14 353.06,535.94 351.79,534.67 351.79,464.82 353.06,463.55 353.06,462.28 IC81.14 | 431.8,534.67 433.07,535.94 IC102.14 | 431.8,534.67 431.8,496.57 | 431.8,444.5 431.8,416.56 | 431.8,416.56 431.8,405.13 433.07,403.86 433.07,377.19 IC97.14 | 274.32,558.8 278.13,562.61 278.13,573.4 M916_13.A2 | 274.32,558.8 273.05,557.53 IC69.14 | 277.5,526.41 v277.5,536.58 277.5,544.2 274.32,547.37 274.32,558.8 | 277.5,526.41 277.5,498.48 278.13,497.84 M916_12.A2 | 277.5,526.41 273.69,526.41 273.69,478.15 IC68.14 274.32,476.25 273.05,474.98 273.05,443.23 IC67.14 273.05,440.69 271.78,439.42 271.78,406.4 273.05,405.13 IC66.14 273.05,402.59 271.78,401.32 271.78,394.33 273.05,393.06 273.05,367.03 IC65.14 273.05,364.49 271.78,363.22 271.78,330.2 273.05,328.93 IC64.14 273.05,326.39 271.78,325.12 271.78,318.77 273.05,317.5 273.05,290.83 IC63.14 273.05,288.29 271.78,287.02 271.78,280.67 272.42,280.04 272.42,252.09 IC62.14 273.05,250.19 271.78,248.92 271.78,196.85 273.05,195.58 IC61.14 273.05,193.04 271.78,191.77 271.78,184.78 273.05,183.51 273.05,119.38 IC60.14 273.05,116.84 273.05,113.03 271.78,111.76 271.78,44.45 273.05,43.18 IC59.14 273.05,40.64 271.78,39.37 271.78,19.05 274.32,16.51 274.32,2.54 280.04,-3.17 IC58.4 | IC70.14 312.42,5.08 311.15,6.35 311.15,39.37 312.42,40.64 IC71.14 312.42,43.18 317.5,48.26 317.5,59.05 M916_14.A2 317.5,59.69 316.23,60.96 316.23,74.93
  Top 0.254: 316.23,74.93 312.42,78.74 IC72.14 | 316.23,105.41 316.23,74.93 | 316.23,105.41 316.23,133.99 317.5,135.25 M916_15.A2 | 316.23,105.41 311.15,110.49 311.15,116.84 312.42,118.11 IC73.14 312.42,120.65 311.15,121.92 311.15,177.8 | 311.15,177.8 312.42,176.53 IC74.14 | 311.15,177.8 311.15,193.04 312.42,194.31 IC75.14 312.42,196.85 312.42,206.38 v313.69,207.65 311.15,210.19 311.15,254 | 311.15,254 312.42,252.73 IC76.14 | 311.15,254 311.15,271.78 | 311.15,271.78 312.42,273.05 IC77.14 | 311.15,271.78 311.15,309.25 | 311.15,309.25 311.15,363.22 312.42,364.49 IC78.14 | 311.15,309.25 v311.79,309.25 | IC29.8 156.21,364.49 157.48,363.22 157.48,330.2 156.21,328.93 IC28.8 156.21,326.39 155.57,325.75 155.57,321.94 154.94,321.31 154.94,287.02 | 154.94,248.92 156.21,250.19 IC26.8 | 154.94,248.92 154.94,215.9 156.21,214.63 IC25.8 156.21,212.09 157.48,210.82 157.48,177.8 156.21,176.53 IC24.8 156.21,173.99 154.31,172.09 154.31,102.23 152.4,100.33 IC23.14 152.4,97.79 153.67,96.52 153.67,25.4 152.4,24.13 IC22.14 | 154.94,287.02 156.21,288.29 IC27.8 | 154.94,287.02 154.94,248.92 | 195.58,401.32 195.58,368.3 196.85,367.03 IC40.8 | 195.58,401.32 196.85,402.59 IC41.8 | 195.58,401.32 195.58,439.42 196.85,440.69 IC42.8 196.85,443.23 194.94,445.13 194.94,476.88 196.85,478.79 IC43.8 196.85,481.33 195.58,482.6 195.58,515.62 196.85,516.89 IC44.8 | IC33.8 156.21,593.09 152.4,589.28 152.4,557.53 IC32.14 152.4,554.99 151.13,553.72 151.13,482.6 152.4,481.33 IC31.14 | IC57.4 240.03,566.42 238.76,565.15 v238.76,555.62 238.76,532.13 240.03,530.86 IC56.4 240.03,528.32 v240.03,522.61
  Top 0.254: M916_19.A2 -43.18,224.79 -43.81,225.43 -43.81,236.22 -43.18,236.85 M916_20.A2 -43.18,237.49 -43.81,238.12 -43.81,312.42 -43.18,313.06 M916_21.A2 -43.18,313.69 -43.81,314.32 -43.81,388.62 -43.18,389.25 M916_22.A2 | v-8.89,271.78 -8.89,297.18 | -8.89,297.18 -7.62,298.45 IC2.14 | -8.89,297.18 -8.89,334.01 -8.26,334.64 -8.26,338.45 -7.62,339.09 IC3.14 | IC15.14 34.29,481.33 34.92,481.96 34.92,499.75 35.56,500.38 35.56,506.73 34.29,508 IC6.14 34.29,510.54 37.47,513.72 37.47,572.77 38.1,573.4 M916_4.A2 | IC7.14 -7.62,548.64 -8.89,549.91 -8.89,582.93 -7.62,584.2 IC8.14 | M916_23.A2 -43.18,466.09 -43.81,466.73 -43.81,477.52 -43.18,478.15 M916_3.A2 | IC4.14 -7.62,425.45 -8.89,426.72 -8.89,447.04 -7.62,448.31 IC5.14 | IC19.14 73.66,267.97 72.39,266.7 72.39,252.73 IC18.14 72.39,250.19 76.2,246.38 76.2,226.06 77.47,224.79 M916_1.A2 77.47,224.16 76.83,223.52 76.83,210.82 | 76.83,210.82 76.83,136.53 77.47,135.89 M916_6.A2 78.74,135.25 78.74,101.6 | 76.83,210.82 77.47,211.46 M916_7.A2 | 76.83,59.05 72.39,59.05 72.39,24.13 IC16.14 | 76.83,59.05 77.47,59.05 M916_5.A2 | IC13.14 33.02,267.97 31.75,266.7 31.75,209.55 33.02,208.28 33.02,195.58 IC12.14 33.02,193.04 31.75,191.77 31.75,154.94 33.02,153.67 33.02,119.38 IC11.14 33.02,116.84 31.75,115.57 31.75,109.22 33.02,107.95 33.02,62.23 IC10.14 33.02,59.69 33.02,55.88 34.29,54.61 34.29,46.99 36.83,44.45 36.83,20.95 34.92,20.95 33.66,22.23 IC9.14 | 78.74,101.6 78.74,68.58 76.83,66.67 76.83,59.05 | IC53.14 232.41,288.29 231.14,287.02 231.14,280.67 232.41,279.4 232.41,275.59 236.22,271.78 IC52.8 236.22,269.24 234.95,267.97 234.95,229.87
  Top 0.254: v232.41,117.47 232.41,100.33 IC47.14 232.41,97.79 231.14,96.52 231.14,25.4 232.41,24.13 IC46.14 | IC48.8 236.22,119.38 237.49,120.65 237.49,153.67 236.22,154.94 IC49.8 236.22,157.48 234.95,158.75 234.95,191.77 236.22,193.04 IC50.8 236.22,195.58 236.22,207.65 v235.59,208.28 234.95,208.91 234.95,229.87 | 234.95,229.87 236.22,231.14 IC51.8 | 195.58,96.52 195.58,63.5 196.85,62.23 IC35.8 196.85,59.69 195.58,58.42 195.58,27.94 196.85,26.67 196.85,24.13 IC34.8 | 195.58,96.52 196.85,97.79 IC36.8 | 195.58,96.52 195.58,134.62 196.85,135.89 IC37.8 | v78.11,101.6 78.74,101.6
  Bottom 0.254: IC129.11 600.08,165.74 598.8,164.47 597.53,164.47 596.26,165.74 IC129.13 | IC130.11 600.08,203.84 598.8,202.56 597.53,202.56 596.26,203.84 IC130.13 | IC131.14 593.73,241.94 595,241.94 IC131.13 596.26,241.94 597.53,240.66 598.8,240.66 600.08,241.94 IC131.11 | v391.8,144.78 425.45,144.78 432.44,137.79 IC93.14 | v389.89,250.82 391.8,250.82 IC87.14 | 511.18,20.95 476.25,20.95 | 476.25,20.95 434.98,20.95 433.7,22.23 IC92.14 432.44,22.86 395.61,22.86 v394.97,22.23 | 511.18,20.95 512.45,22.23 IC112.14 | 511.18,20.95 550.54,20.95 551.82,22.23 IC123.14 | IC104.14 473.07,13.34 474.35,13.34 IC104.13 475.62,14.61 476.88,15.88 478.15,15.88 479.43,14.61 IC104.11 | IC105.14 473.07,51.44 474.35,51.44 IC105.13 475.62,51.44 476.88,50.16 478.15,50.16 479.43,51.44 IC105.11 | 476.25,20.95 v476.25,21.59 | v545.47,521.34 475.62,521.34 473.07,518.79 IC111.14 | v511.81,436.25 545.47,436.25 IC124.24 | IC96.14 433.7,337.19 434.98,337.19 IC96.13 | IC97.14 433.7,375.29 434.98,375.29 IC97.13 436.25,375.29 437.51,374.01 442.6,374.01 | 442.6,374.01 461.64,374.01 471.81,384.18 IC110.14 473.07,385.44 474.35,386.71 511.18,386.71 512.45,385.44 IC119.14 | 442.6,374.01 441.32,375.29 IC97.11 | IC80.14 353.69,384.18 354.96,382.9 390.52,382.9 391.8,384.18 IC88.14 | IC103.11 440.06,586.11 438.79,587.38 437.51,587.38 436.25,586.11 IC103.13 | IC98.11 440.06,413.38 438.79,412.12 437.51,412.12 436.25,413.38 IC98.13 | IC81.14 353.69,460.38 354.96,459.11 v390.52,459.11 421.64,459.11 422.91,460.38 432.44,460.38 IC100.14 | IC135.14 592.46,327.02 591.18,325.75 514.99,325.75 513.72,327.02 IC118.14
  Bottom 0.254: IC60.14 273.69,118.75 274.95,120.02 311.79,120.02 IC73.14 | v313.69,207.65 317.5,211.46 M916_16.A2 | v311.79,309.25 352.43,309.25 IC79.14 | IC20.14 73.03,327.02 74.3,325.75 152.4,325.75 153.67,327.02 155.57,327.02 IC28.8 | IC39.14 192.41,288.93 189.87,286.38 159.38,286.38 156.84,288.93 IC27.8 | 194.94,405.76 196.22,404.5 IC41.8 | 194.94,405.76 194.31,406.4 154.94,406.4 153.03,404.5 IC30.14 | 194.94,405.76 230.5,405.76 231.78,404.5 IC54.14 | IC21.14 113.67,555.62 114.94,554.36 150.5,554.36 151.76,555.62 IC32.14 153.03,555.62 154.94,553.72 163.83,553.72 164.47,554.36 191.13,554.36 192.41,555.62 IC45.14 | 230.5,520.07 198.75,520.07 197.49,518.79 IC44.8 | 230.5,520.07 231.78,518.79 IC55.14 | IC31.14 153.03,480.69 154.31,481.96 194.94,481.96 196.22,480.69 IC43.8 | v240.03,522.61 237.49,520.07 230.5,520.07 | IC29.8 156.84,366.39 158.12,367.67 194.94,367.67 196.22,366.39 IC40.8 | -12.06,268.61 v-8.89,271.78 | -12.06,268.61 -13.97,266.7 IC1.24 | IC14.14 32.38,365.12 9.53,342.26 -5.71,342.26 -6.99,341 IC3.14 | M916_21.A2 -41.91,313.06 -41.91,302.26 -10.16,302.26 -8.26,300.36 IC2.14 | M916_4.A2 38.1,574.04 36.2,575.95 -5.71,575.95 -6.35,576.58 -6.35,584.2 -7.62,584.2 IC8.14 | -41.91,394.33 -41.91,389.89 M916_22.A2 | -41.91,394.33 -40.01,394.33 -10.79,423.55 -8.26,423.55 IC4.14 -6.99,424.81 -5.71,426.08 33.66,426.08 38.1,421.64 M916_2.A2 | -41.91,394.33 -43.81,394.33 -43.81,396.88 -43.18,397.51 -43.18,465.45 M916_23.A2 -41.91,466.09 -40.01,466.09 -35.56,470.54 24.77,470.54 33.66,479.43 IC15.14 | IC9.14 33.66,23.5 34.92,24.77 70.48,24.77 71.75,23.5 IC16.14
  Bottom 0.254: v232.41,117.47 235.59,117.47 IC48.8 | v235.59,208.28 198.12,208.28 193.68,212.72 IC38.14 | IC17.14 73.03,99.69 74.93,101.6 v78.11,101.6 149.86,101.6 151.76,99.69 IC23.14 | 194.94,24.77 154.31,24.77 153.03,23.5 IC22.14 | 194.94,24.77 196.22,23.5 IC34.8 | 194.94,24.77 230.5,24.77 231.78,23.5 IC46.14 | -12.06,268.61 -10.16,266.7 -10.16,264.16 -9.53,263.52 -3.17,263.52 -2.54,264.16 -2.54,267.97 -0.64,267.97 0,268.61 32.38,268.61 IC13.14 | v238.76,555.62 272.42,555.62 IC69.14 | v277.5,536.58 352.43,536.58 IC82.14
W+UTS  (via drill 0.61)
  Top 0.254: 76.2,271.14 73.03,271.14 71.12,269.24 71.12,246.38 72.39,245.11 IC18.1 | 76.2,271.14 76.2,270.51 IC19.13 | v492.76,306.7 v492.76,323.21 | v76.2,308.61 76.2,271.14
  Bottom 0.254: v492.76,323.21 492.12,323.21 488.31,327.02 IC109.8 | v492.76,306.7 358.77,306.7 356.87,308.61 356.87,311.79 301.62,311.79 298.45,308.61 271.78,308.61 271.14,309.25 76.83,309.25 v76.2,308.61
W-INH\  (via drill 0.61)
  Top 0.254: v274.95,525.14 274.95,479.43 275.59,478.79 275.59,472.44 276.86,471.17 IC68.2 | v332.74,262.25 332.74,76.83 329.56,73.66 329.56,-5.71 327.02,-5.71 326.39,-5.08 326.39,-1.27 322.58,2.54 IC70.10 | v269.24,266.06 268.61,266.7 268.61,350.52 265.43,353.69 v265.43,464.82
  Bottom 0.254: v274.95,525.14 258.44,541.65 211.46,541.65 210.82,541.02 77.47,541.02 73.03,536.58 -8.89,536.58 -8.89,548.64 -8.26,549.27 3.17,549.27 4.45,548 IC7.9 | v332.74,262.25 331.47,263.52 297.81,263.52 294.64,266.7 269.88,266.7 v269.24,266.06 | v265.43,464.82 268.61,468 274.95,468 276.23,469.26 IC68.2
WB00  (via drill 0.61)
  Top 0.254: v563.25,76.83 576.58,90.17 v576.58,154.94 | M916_5.N2 112.39,56.52 111.12,57.78 v111.12,80.64 111.12,193.68 99.06,205.74 99.06,210.82 102.23,214 102.23,277.5 104.78,280.04 104.78,343.54 108.58,347.35 v108.58,358.77 108.58,379.73 v113.67,384.81 | v316.23,387.99 315.6,388.62 315.6,568.96 314.32,570.23 M916_13.N2 | v527.05,82.55 527.05,74.93 525.78,73.66 IC113.6
  Bottom 0.254: v563.25,76.83 530.23,76.83 526.41,73.03 IC113.6 | v576.58,154.94 578.49,156.84 593.73,156.84 595,158.12 IC129.2 | v108.58,358.77 113.67,363.86 115.57,363.86 M916_9.P2 | v316.23,387.99 309.88,381.63 222.25,381.63 219.07,384.81 v113.67,384.81 | v527.05,82.55 519.43,90.17 325.75,90.17 322.58,87 309.88,87 303.53,80.64 v111.12,80.64
WB00\  (via drill 0.61)
  Top 0.254: v448.31,564.51 448.31,571.5 443.23,576.58 IC103.5 | v464.82,548 501.65,511.18 501.65,241.3 504.19,238.76 v504.19,74.93
  Bottom 0.254: IC103.5 442.6,577.22 440.69,575.31 318.77,575.31 317.5,574.04 M916_13.P2 | IC113.5 523.24,73.66 523.24,74.93 v504.19,74.93 468,74.93 459.11,66.04 370.84,66.04 369.57,67.31 320.68,67.31 320.04,66.67 319.4,66.67 318.77,67.31 115.57,67.31 108.58,60.33 108.58,57.78 114.3,57.78 115.57,59.05 M916_5.P2 | v448.31,564.51 v464.82,548
WB01  (via drill 0.61)
  Top 0.254: M916_14.N2 353.69,56.52 354.33,57.15 354.33,83.82 v353.69,84.45 351.79,86.36 351.79,196.85 v351.15,197.49 | v590.55,193.68 590.55,231.14 593.09,233.68 IC131.1 | v541.65,161.93 v541.65,93.34 | v120.02,263.52 120.65,264.16 120.65,360.05 120.02,360.68 M916_9.R2 | v169.54,262.25 171.45,260.35 v171.45,206.38
  Bottom 0.254: v353.69,84.45 523.88,84.45 527.68,80.64 IC113.8 528.96,80.64 v541.65,93.34 | v590.55,193.68 558.8,161.93 v541.65,161.93 | v120.02,263.52 121.28,262.25 v169.54,262.25 | v171.45,206.38 177.8,200.03 278.76,200.03 279.4,200.66 347.98,200.66 v351.15,197.49
WB01\  (via drill 0.61)
  Top 0.254: v487.68,78.11 487.68,58.42 482.6,53.34 IC105.10
  Bottom 0.254: v487.68,78.11 523.88,78.11 525.14,79.38 IC113.9 | M916_14.P2 356.87,59.05 358.14,57.78 476.88,57.78 481.96,52.7 IC105.10
WB02  (via drill 0.61)
  Top 0.254: v530.86,113.03 535.3,117.47 v535.3,168.28 534.03,169.54 534.03,181.61 535.3,182.88 v535.3,311.79 | v78.11,539.12 78.11,570.23 74.3,570.23 M916_4.N2 | v121.28,517.52 123.83,514.99 123.83,365.12 123.19,364.49 M916_9.S2 123.19,363.86 123.19,344.17 v127,340.36 | v389.89,315.6 389.25,316.23 v389.25,335.28
  Bottom 0.254: v530.86,113.03 528.32,113.03 526.41,111.12 IC114.6 | v535.3,168.28 561.98,194.94 593.73,194.94 595,196.22 IC130.2 | v78.11,539.12 99.69,517.52 v121.28,517.52 | v535.3,311.79 531.5,315.6 v389.89,315.6 | v389.25,335.28 387.99,336.55 306.7,336.55 300.99,342.26 205.74,342.26 203.84,340.36 v127,340.36
WB02\  (via drill 0.61)
  Top 0.254: v488.95,107.31 488.95,58.42 483.87,53.34 483.87,50.8 481.33,48.26 481.33,8.89 482.6,7.62 IC104.5 | v448.31,581.66 510.54,519.43 510.54,212.72 511.18,212.09 511.18,210.19 509.27,208.28 v509.27,107.31
  Bottom 0.254: v488.95,107.31 v509.27,107.31 520.07,107.31 522.61,109.86 IC114.5 | v448.31,581.66 93.98,581.66 90.81,578.49 77.47,578.49 77.47,574.04 M916_4.P2
WC  (via drill 0.61)
  Top 0.254: IC66.1 273.05,397.51 274.32,398.78 v274.32,405.76 v274.32,448.94 274.32,468.63 IC68.1 | v607.06,412.75 607.06,420.37 605.79,421.64 IC137.9
  Bottom 0.254: v607.06,412.75 603.25,408.94 461.01,408.94 460.38,409.57 358.14,409.57 354.33,405.76 v274.32,405.76 | v274.32,448.94 252.09,448.94 250.82,447.68 58.42,447.68 58.42,440.69 M916_10.H1
WC0  (via drill 0.61)
  Top 0.254: v372.75,142.24 367.03,147.96 367.03,307.34 368.3,308.61 IC79.8
  Bottom 0.254: v372.75,142.24 420.37,142.24 432.44,130.18 IC93.1
WC0\  (via drill 0.61)
  Top 0.254: v564.51,142.24 571.5,149.22 v571.5,412.12
  Bottom 0.254: v564.51,142.24 541.02,142.24 526.41,127.64 437.51,127.64 436.25,128.91 IC93.2 | v571.5,412.12 576.58,417.19 596.26,417.19 596.9,416.56 596.9,413.38 598.8,413.38 599.44,414.02 599.44,420.37 600.71,420.37 602.62,422.27 IC137.10
WC\  (via drill 0.61)
  Top 0.254: v378.46,45.72 390.52,57.78 390.52,160.66 387.99,163.19 387.99,323.85 387.35,324.49 v387.35,362.58 | v476.25,362.58 477.52,363.86 477.52,375.92 IC110.3 477.52,378.46 478.79,379.73 478.79,393.7 v480.06,394.97
  Bottom 0.254: 607.06,414.02 605.79,412.75 595.63,412.75 595.63,414.02 IC137.2 | 607.06,414.02 607.06,422.27 607.7,422.27 IC137.8 | v378.46,45.72 321.31,45.72 318.13,42.55 IC71.12 | v476.25,362.58 v387.35,362.58 | 607.06,414.02 608.33,412.75 608.33,394.97 v480.06,394.97
WR_EN  (via drill 0.61)
  Top 0.254: 81.28,571.5 81.28,596.9 431.8,596.9 442.6,586.11 IC103.10 443.87,584.84 456.56,572.13 456.56,405.13 455.93,404.5 v455.93,368.3 | 81.28,571.5 80.64,570.87 M916_4.R2 | 81.28,571.5 81.28,556.89 80.64,556.26 80.64,539.12 56.52,514.99 56.52,438.79 55.24,437.51 M916_10.F1 | v515.62,153.03 514.35,154.31 514.35,200.66 513.08,201.93 IC116.1 | IC129.3 598.17,160.02 598.17,165.1 IC129.12 598.17,167.64 598.17,195.58 IC130.3 598.17,198.12 598.17,203.2 IC130.12 598.17,205.74 598.17,233.68 IC131.3 598.17,236.22 598.17,241.3 IC131.12 | v479.43,297.81 479.43,316.87 477.52,318.77 IC109.3 477.52,321.31 477.52,323.85 476.25,325.12 476.25,328.93 474.98,330.2 474.98,366.39 v473.71,367.67 | v524.51,292.74 524.51,250.19 523.24,248.92 523.24,245.11 IC117.5 523.24,242.57 523.24,234.31 v520.7,231.78 | v359.41,42.55 359.41,55.88 M916_14.R2 | v506.1,152.4 505.46,151.76 v505.46,45.09
  Bottom 0.254: IC115.6 525.14,149.22 521.34,153.03 v515.62,153.03 514.99,152.4 v506.1,152.4 | IC117.5 523.88,243.21 531.5,235.59 583.57,235.59 592.46,244.47 596.26,244.47 597.53,243.21 IC131.12 | v479.43,297.81 484.5,292.74 v524.51,292.74 | v520.7,231.78 508.63,231.78 508.63,208.91 513.08,204.47 IC116.1 | 480.69,42.55 481.96,43.81 IC105.5 | 480.69,42.55 v359.41,42.55 | M916_5.R2 120.02,55.88 121.28,54.61 190.5,54.61 191.77,55.88 319.4,55.88 321.31,53.98 356.87,53.98 358.77,55.88 M916_14.R2 | v505.46,45.09 502.92,42.55 480.69,42.55 | v455.93,368.3 456.56,367.67 v473.71,367.67
WR_EN\  (via drill 0.61)
  Top 0.254: IC106.9 485.14,119.38 487.68,121.92 v487.68,147.96 484.5,151.13 484.5,184.78 483.87,185.42 483.87,245.11 | v518.79,214 513.08,219.71 513.08,242.57 IC117.1 | v2.54,321.31 3.17,320.68 3.17,301.62 2.54,300.99 IC2.10 | IC109.9 485.14,326.39 483.87,325.12 v483.87,316.87 483.87,245.11 | 483.87,245.11 v485.14,243.84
